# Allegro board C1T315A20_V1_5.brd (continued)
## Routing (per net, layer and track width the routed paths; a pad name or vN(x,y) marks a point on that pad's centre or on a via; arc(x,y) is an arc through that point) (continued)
TL_PA7_SWS: length 27.7
  TOP w0.2: U8.13 v1(30.27,47.78) ; R11.1 12.45,58.73 R36.1 v1(13.88,60.78)
  BOTTOM w0.2: v1(30.27,47.78) 26.59,47.78 13.88,60.5 v1(13.88,60.78)
TL_PB0: length 94.6
  TOP w0.2: 59.58,14.53 59.05,14.53 51.85,21.73 51.85,29.36 49.48,31.73 49.48,32.5 46.15,35.83 46.15,39.55 v1(46.58,39.98) ; v1(41.77,39.98) 34.01,39.98 31.23,42.77 31.23,44.67 30.62,45.27 U8.14 ; J3.3 J3.1
  BOTTOM w0.2: J3.3 70.65,53.3 67.55,56.41 59.24,56.41 58.49,57.16 54.66,57.16 49.05,51.55 49.05,42.45 v1(46.58,39.98) v1(41.77,39.98)
TL_PB1: length 60.3
  TOP w0.2: U8.15 30.98,45.41 31.58,44.81 31.58,42.91 33.98,40.5 v1(41.33,40.5) ; v1(46.15,40.5) 49.9,40.5 50.55,39.86 50.55,37.25 49.83,36.53 49.83,32.05 52.17,29.7 52.17,29.53 52.2,29.5 52.2,22.24 58.91,15.53 61.35,15.53 62.36,14.53 J6.33
  BOTTOM w0.2: v1(41.33,40.5) v1(46.15,40.5)
TL_PB2: length 52.5
  TOP w0.2: U8.16 31.33,45.56 31.92,44.96 31.92,43.05 33.98,41 v1(42.08,41) ; 59.58,17.07 57.87,17.07 52.55,22.38 52.55,29.82 50.17,32.19 50.17,36.35 50.9,37.08 50.9,40.05 49.95,41 v1(46.65,41)
  BOTTOM w0.2: v1(46.65,41) v1(42.08,41)
TL_PB3: length 58.4
  TOP w0.2: v1(46.15,41.5) 49.95,41.5 51.25,40.21 51.25,36.93 50.52,36.21 50.52,32.34 52.98,29.89 52.98,22.45 57.46,17.96 61.47,17.96 62.36,17.07 65.88,17.07 ; U8.17 31.67,45.7 32.27,45.1 32.27,43.2 33.97,41.5 v1(41.17,41.5)
  BOTTOM w0.2: v1(46.15,41.5) v1(41.17,41.5)
TL_PB4: length 49.2
  TOP w0.2: U8.18 32.02,45.85 32.62,45.25 32.62,43.34 33.97,42.01 v1(42.1,42.01) ; 59.58,19.61 58.83,19.61 53.33,25.11 53.33,30.03 50.88,32.48 50.88,36.06 51.6,36.79 51.6,40.38 49.98,42.01 v1(46.7,42.01)
  BOTTOM w0.2: v1(46.7,42.01) v1(42.1,42.01)
TL_PB5: length 55
  TOP w0.2: J6.29 65.33,19.61 63.69,21.24 58.09,21.24 53.73,25.61 53.73,30.24 51.23,32.74 51.23,35.92 51.95,36.64 51.95,40.56 49.88,42.63 v1(46.15,42.63) ; U8.19 32.38,45.99 32.98,45.4 32.98,43.49 34.11,42.35 41,42.35 v1(41.27,42.63)
  BOTTOM w0.2: v1(46.15,42.63) v1(41.27,42.63)
TL_PB6: length 47.2
  TOP w0.2: v1(46.75,43.13) 49.92,43.13 52.3,40.75 52.3,36.5 51.58,35.77 51.58,32.89 54.08,30.39 54.08,26.03 57.96,22.14 59.58,22.14 ; v1(42.05,43.13) 40.5,43.13 40.12,42.76 34.2,42.76 33.33,43.63 33.33,45.54 32.73,46.14 U8.20
  BOTTOM w0.2: v1(46.75,43.13) v1(42.05,43.13)
TL_PB7: length 53.2
  TOP w0.2: 65.88,22.14 65.21,22.14 64.31,23.05 57.55,23.05 54.48,26.12 54.48,30.48 51.92,33.03 51.92,35.63 52.65,36.35 52.65,40.91 49.78,43.78 v1(46.15,43.78) ; v1(41.65,43.78) 40.6,43.78 40.02,43.2 34.25,43.2 33.67,43.78 33.67,45.69 33.08,46.28 U8.21
  BOTTOM w0.2: v1(46.15,43.78) v1(41.65,43.78)
TL_PC0: length 35
  TOP w0.2: v1(53.12,34.55) 55.15,32.53 56.3,32.53 59.06,29.77 59.58,29.77 ; v1(39.23,43.74) 39.21,43.74 34.8,48.16 34.3,48.16
  BOTTOM w0.2: v1(53.12,34.55) 50.35,37.33 48.88,37.33 47.77,38.43 40.91,38.43 39.23,40.11 v1(39.23,43.74)
TL_PC1: length 34.5
  TOP w0.2: v1(39.83,44.24) 39.26,44.24 35,48.51 U8.25 ; v1(53.27,35.28) 55.65,32.91 58.33,32.91 58.92,32.3 59.58,32.3
  BOTTOM w0.2: v1(39.83,44.24) 39.8,44.21 39.8,43.91 39.8,43.91 39.8,43.5 39.8,43.5 39.8,40.03 41.05,38.78 47.92,38.78 49.02,37.68 50.88,37.68 v1(53.27,35.28)
TL_PC2: length 34.1
  TOP w0.2: v1(55.23,35.23) 58.01,35.23 58.39,34.84 59.58,34.84 ; v1(39.42,44.85) 39.35,44.85 39.35,44.83 39.17,44.83 35.15,48.85 U8.26
  BOTTOM w0.2: v1(55.23,35.23) 53.85,36.61 52.65,36.61 51.23,38.03 49.16,38.03 48.06,39.13 41.3,39.13 40.15,40.28 40.15,42.9 40.38,43.13 40.38,44.63 40.17,44.83 39.35,44.83 39.35,44.85 v1(39.42,44.85)
TL_PC3: length 33.4
  TOP w0.2: U8.27 35.29,49.2 39.14,45.35 v1(39.9,45.35) ; 59.58,37.39 59.17,36.98 v1(55.23,36.98)
  BOTTOM w0.2: v1(55.23,36.98) 52.81,36.98 51.42,38.38 49.31,38.38 48.21,39.48 41.5,39.48 40.5,40.48 40.5,42.76 40.77,43.03 40.77,44.76 40.17,45.35 v1(39.9,45.35)
TL_PC4_TDI: length 91.9
  TOP w0.2: v1(48.06,39.98) 47.35,39.27 v1(47.35,37.88) ; 59.58,42.47 59.4,42.28 v1(53.02,42.28) ; U8.32 35.81,50.95 36.71,50.05 39.23,50.05 43.08,46.2 43.08,39.86 40.75,37.53 40.75,37.31 v1(40.55,37.11) 39.82,36.38 18.48,36.38 18.12,36.73 16.9,36.73 v1(16.82,36.66)
  BOTTOM w0.2: v1(40.55,37.11) 40.84,37.41 46.88,37.41 v1(47.35,37.88) ; v1(53.02,42.28) 51.03,42.28 48.72,39.98 v1(48.06,39.98) ; v1(16.82,36.66) 16.82,43.73 8.3,52.26 8.3,53.21 7.5,54.01 5.63,54.01 J4.12
TL_PC5_TDO: length 89.6
  TOP w0.2: 40.62,36.33 40.62,36.25 40.55,36.25 40.33,36.03 18.33,36.03 18.13,36.23 v1(17.73,36.23) ; 40.62,36.33 40.62,36.41 41.1,36.88 41.1,37.39 43.42,39.71 43.42,46.35 39.37,50.41 36.85,50.41 35.95,51.3 U8.33 ; 40.62,36.33 v1(40.55,36.33) ; 59.58,39.92 58.15,39.92 57.1,38.88 v1(55.85,38.88) ; v1(49.67,39.98) 48.85,39.98 47.88,39 47.88,37.68 v1(47.4,37.2)
  BOTTOM w0.2: v1(17.73,36.23) 17.65,36.16 16.62,36.16 16.32,36.45 16.32,43.56 J4.11 ; v1(47.4,37.2) 47.25,37.05 41.2,37.05 40.55,36.41 v1(40.55,36.33) ; v1(49.67,39.98) 51.85,39.98 52.95,38.88 v1(55.85,38.88)
TL_PC6_TMS: length 113.8
  TOP w0.2: J6.11 65.31,42.47 61.62,38.78 57.73,38.78 57.2,38.25 v1(55.2,38.25) ; v1(46.65,36.55) 47.5,36.55 48.27,37.33 48.27,38.66 v1(49.08,39.45) ; 34.3,51.66 36.1,51.66 37,50.76 39.55,50.76 43.77,46.53 43.77,39.56 41.45,37.24 41.45,36.52 v1(41.31,36.37) 40.61,35.68 16.93,35.68 v1(16.75,35.5)
  BOTTOM w0.2: v1(49.08,39.45) 51.65,39.45 52.85,38.25 v1(55.2,38.25) ; v1(16.75,35.5) 15.97,36.28 15.97,43.41 7.83,51.55 4.16,51.55 3.33,52.38 3.33,55.87 4.01,56.55 5.07,56.55 5.63,57.11 5.63,61.87 J4.4 ; v1(41.31,36.37) 41.49,36.55 v1(46.65,36.55)
TL_PC7_TCK: length 112.7
  TOP w0.2: v1(41.31,35.67) 41.27,35.67 ; 41.27,35.67 41.27,35.7 41.38,35.7 41.85,36.18 41.85,37.14 44.12,39.42 44.12,46.67 39.7,51.1 37.15,51.1 36.24,52.01 U8.35 ; 41.27,35.67 40.94,35.33 18.02,35.33 v1(17.77,35.08) ; v1(47.05,36.05) 47.49,36.05 48.66,37.22 48.66,38.3 49.32,38.95 v1(49.7,38.95) ; v1(54.6,37.53) 57.17,37.53 57.95,38.3 63.7,38.3 65.32,39.92 J6.13
  BOTTOM w0.2: 4.49,60.48 1.72,57.72 1.72,52.93 3.45,51.2 7.69,51.2 15.62,43.27 15.62,35.92 16.54,35 17.7,35 v1(17.77,35.08) ; v1(41.31,35.67) 41.7,36.05 v1(47.05,36.05) ; v1(54.6,37.53) 52.83,37.53 51.4,38.95 v1(49.7,38.95)
TL_PD0_AMIC: length 72.8
  TOP w0.2: 59.58,6.9 59.58,9.45 59.11,9.45 58.12,10.43 58.12,11.91 45.27,24.76 45.27,55.51 42.5,58.28 37.28,58.28 36.99,58.57 36.98,58.57 36.25,59.3 33.11,59.3 30.62,56.82 U8.53
TL_PD1_MICBIAS: length 69
  TOP w0.2: 59.58,11.98 58.72,11.98 45.65,25.05 45.65,55.63 42.65,58.63 37.42,58.63 37.13,58.92 37.13,58.92 36.83,59.21 36.83,59.22 36.4,59.66 32.97,59.66 30.27,56.97 U8.54
TL_PD2_32K: length 16
  TOP w0.2: R34.2 39.33,62.01 C21.2 Y2.1 38.09,64.25 R1.1 37.42,63.8 35.66,62.04 35.66,61.22 34.45,60.01 32.82,60.01 29.92,57.11 U8.55
TL_PD2_NC_32K: length 48
  TOP w0.2: R34.1 41.15,62.01 46.73,56.43 46.73,47.25 49.85,44.13 49.92,44.13 53,41.05 53,36.21 52.27,35.48 52.27,33.18 54.98,30.48 54.98,26.12 56.41,24.69 59.58,24.69
TL_PD3_32K: length 18.5
  TOP w0.2: R35.2 39.62,64.24 Y2.2 ; Y2.2 38.4,65.52 C22.2 ; Y2.2 38.14,65.25 R1.2 36.62,64.45 36.62,63.53 35.31,62.22 35.31,61.37 34.3,60.35 32.67,60.35 29.58,57.26 U8.56
TL_PD3_NC_32K: length 45
  TOP w0.2: R35.1 47.08,56.58 47.08,47.4 49.99,44.48 50.07,44.48 53.35,41.2 53.35,36.06 52.62,35.34 52.62,33.32 55.33,30.62 55.33,30.32 58.42,27.23 59.58,27.23
TL_PD4: length 40.6
  TOP w0.2: v1(47.7,48.6) 47.7,49.2 50.45,51.95 56.37,51.95 59.58,55.16 ; v1(28.18,56.8) U8.60
  BOTTOM w0.2: v1(28.18,56.8) 27.7,56.8 C123.1 28.35,55.85 28.35,54.63 30.15,52.83 34.26,52.83 36.66,50.43 41.41,50.43 43.24,48.6 v1(47.7,48.6)
TL_PD5: length 37
  TOP w0.2: 59.58,50.09 50.08,50.09 48.35,48.35 v1(48.35,48.01) ; U8.61 v1(27.82,55.2)
  BOTTOM w0.2: 27.82,55.21 v1(27.82,55.2) 27.82,54.71 C124.1 27.83,54.6 29.95,52.48 34.11,52.48 36.51,50.08 41.27,50.08 43.34,48.01 v1(48.35,48.01)
TL_PD6: length 39.8
  TOP w0.2: v1(48.38,49.1) 50.77,51.51 57.9,51.51 59.02,52.62 59.58,52.62 ; v1(27.48,57.38) U8.62
  BOTTOM w0.2: v1(48.38,49.1) 43.25,49.1 41.58,50.78 36.8,50.78 34.4,53.18 30.3,53.18 28.7,54.77 28.7,56.81 C125.1 28.42,57.38 v1(27.48,57.38)
TL_PD7: length 38
  TOP w0.2: v1(47.7,47.48) 59.51,47.48 59.58,47.55 ; U8.63 v1(27.12,55.2)
  BOTTOM w0.2: v1(47.7,47.48) 43.38,47.48 41.12,49.73 36.37,49.73 33.97,52.13 28.1,52.13 27.32,52.91 27.32,54.16 C126.1 26.83,54.7 27.12,55 v1(27.12,55.2)
TL_PE0: length 26.6
  TOP w0.2: J7.2 4.26,47.66 5.88,49.28 12.36,49.28 18.23,55.16 25.2,55.16
TL_PE1: length 27.5
  TOP w0.2: J7.4 2.21,45.12 6.03,48.93 12.5,48.93 18.38,54.8 U8.68
TL_PE2: length 29.6
  TOP w0.2: U8.69 18.52,54.45 12.64,48.58 6.17,48.58 3.3,45.71 3.3,43.7 2.17,42.58 J7.6
TL_PE3: length 19.9
  TOP w0.2: U8.70 18.66,54.1 12.79,48.23 9.15,48.23 8.58,47.66 J7.1
TL_PE4: length 20.8
  TOP w0.2: J7.3 10.18,45.12 18.81,53.76 25.2,53.76
TL_PE5: length 22.7
  TOP w0.2: J7.5 9.85,42.58 12.2,44.93 12.2,46.62 18.98,53.41 U8.72
TL_PE6: length 24
  TOP w0.2: U8.73 19.13,53.05 12.55,46.48 12.55,44.66 10,42.1 10,41.53 8.51,40.04 J7.7
TL_PE7: length 26.1
  TOP w0.2: J7.9 8.47,37.5 9.43,38.45 9.43,40.46 10.35,41.39 10.35,41.96 12.9,44.51 12.9,46.33 19.27,52.7 U8.74
TL_PF0: length 34.8
  TOP w0.2: J7.8 2.19,40.04 5.63,36.6 9.28,36.6 9.85,37.17 9.85,39.45 10.95,40.55 10.95,42.03 13.25,44.34 13.25,46.19 19.42,52.35 U8.75
TL_PF1: length 33.9
  TOP w0.2: J7.10 2.23,37.5 3.48,36.25 9.42,36.25 10.2,37.03 10.2,39.31 11.3,40.41 11.3,41.89 13.6,44.19 13.6,46.04 19.57,52.01 U8.76
TL_PF2: length 33.7
  TOP w0.2: 25.2,51.66 19.71,51.66 13.95,45.9 13.95,44.05 11.65,41.75 11.65,40.27 10.55,39.16 10.55,36.88 9.55,35.88 3.15,35.88 2.23,34.96 1.67,34.96
TL_PF3: length 35.4
  TOP w0.2: 1.67,32.42 2.26,32.42 2.85,33 4.9,33 5.96,34.05 9.51,34.05 11.82,36.37 11.82,39.95 12,40.12 12,41.6 14.3,43.9 14.3,45.75 19.86,51.3 U8.78
TL_PF4: length 32
  TOP w0.2: 1.67,29.88 2.28,29.88 6.1,33.7 9.65,33.7 12.18,36.23 12.18,39.8 12.35,39.98 12.35,41.45 14.65,43.76 14.65,45.6 19.8,50.76 R44.1
TL_PF4_SDMP1: length 40.1
  TOP w0.2: TP6.1 41.9,19.33 L15.1 41.05,19.33 38.23,22.16 18.1,22.16 12.57,27.69 10.77,27.69 8.57,29.88 J7.15
TL_PF5: length 34
  TOP w0.2: 1.67,27.34 2.13,27.34 3.35,28.55 3.35,30.46 6.24,33.36 10.06,33.36 12.45,35.75 12.45,35.75 12.52,35.83 12.52,39.66 15.15,42.28 15.15,45.61 19.41,49.87 R45.1
TL_PF5_SDMN1: length 35.3
  TOP w0.2: TP7.1 38.2,19.31 L16.1 37.35,19.3 34.9,21.76 18,21.76 12.42,27.34 J7.17
TL_PF6: length 41.4
  TOP w0.2: 25.2,50.26 23.91,50.26 22.98,49.33 19.5,49.33 15.5,45.33 15.5,42.06 12.9,39.46 12.9,34.05 10.18,31.33 6.3,31.33 4.62,29.66 4.62,25.78 3.64,24.8 1.67,24.8
TL_PF7: length 42.3
  TOP w0.2: U8.82 24.05,49.91 23.13,48.98 19.65,48.98 15.85,45.18 15.85,41.88 13.3,39.33 13.3,33.96 10.22,30.88 6.53,30.88 4.97,29.33 4.97,25.56 1.67,22.26
TL_PG0_MOSI: length 13
  TOP w0.2: U2.5 25.5,37.59 24.15,38.93 24.15,43.08 24.8,43.73 26.51,43.73 28.18,45.4 U8.7
TL_PG1_MCLK: length 11.7
  TOP w0.2: 25.93,38.86 25.38,38.86 24.5,39.73 24.5,42.93 24.95,43.38 26.66,43.38 28.52,45.25 U8.8
TL_PG2_MSIO3: length 10.2
  TOP w0.2: U2.7 25.48,40.12 24.85,40.75 24.85,42.78 25.09,43.03 26.8,43.03 28.88,45.1 U8.9
TL_PG3_MSCN: length 47.2
  TOP w0.2: R3.2 21.27,43.63 ; 21.27,43.63 21.73,44.08 26.36,44.08 27.82,45.54 U8.6 ; 21.27,43.63 20.5,42.86 20.5,42.5 v1(20.52,42.48) 20.52,41.39 ; SW2.4 SW2.3 11.9,64.68 v1(11.9,63.73)
  BOTTOM w0.2: v1(11.9,63.73) 11.2,63.03 11.2,53.98 20.52,44.66 v1(20.52,42.48)
TL_PG4_MISO: length 13.6
  TOP w0.2: 20.52,40.12 20.05,40.12 19.43,40.75 19.43,42.28 21.57,44.43 26.22,44.43 27.48,45.69 U8.5
TL_PG5_MSIO2: length 14.8
  TOP w0.2: 20.52,38.86 19,40.38 19,42.35 21.43,44.78 26.07,44.78 27.12,45.83 U8.4
TL_RFVDD_0P94: length 68.7
  TOP w0.2: 26.23,56.85 26.23,56.83 26.43,56.63 U8.65
  TOP w0.3: 24.65,57.23 24.82,57.05 26.02,57.05 26.23,56.85
  TOP w0.5: 22.77,57.55 v1(22.13,57.55) ; 22.77,57.55 C9.1 ; 22.77,57.55 22.85,57.55 22.88,57.58 C8.1 D9.2 24.56,57.32 24.65,57.23
  POWER w0.5: v1(54.62,40.42) 54.51,40.3 52.91,40.3 52.52,39.92 52.52,39.81 46.29,33.58 25.23,33.58 v1(25.2,33.55) ; v1(22.13,57.55) 22.55,57.13 22.55,47.43 v1(22.05,46.93)
  BOTTOM w0.5: v1(25.2,33.55) 25.2,43.78 v1(22.05,46.93) ; 59.58,39.91 55.14,39.91 v1(54.62,40.42)
TL_VBAT: length 77.2
  TOP w0.2: U8.47 v1(32.73,55.2)
  POWER w0.5: v1(38.5,60.1) 39.73,61.33 43.45,61.33 46.52,58.26 54.58,58.26 57.02,55.8 v1(57.02,55.16) ; v1(54.15,39.38) 53.85,39.08 53.85,35.62 53.92,35.55 53.92,35.01 53.85,34.94 53.85,23.83 55.55,22.13 55.55,22.13 v1(55.55,22.13)
  BOTTOM w0.5: v1(54.15,39.38) 53.98,39.55 53.98,41.08 54.92,42.03 54.92,43.43 59.02,47.53 59.58,47.53 59.58,52.61 57.97,52.61 57.02,53.55 v1(57.02,55.16) ; v1(32.73,55.2) 33.02,55.51 D11.2 34.52,55.51 C17.1 35.58,56.55 35.58,58.58 37.1,60.1 v1(38.5,60.1) ; v1(55.55,22.13) 55.85,22.43 59.27,22.43 59.58,22.13 59.58,19.59
TL_VBUS: length 31.5
  TOP w0.2: U8.46 33.08,56.62 33.63,57.18
  TOP w0.35: 33.7,57.26 33.63,57.18
  TOP w0.5: v1(36.23,57.7) 35.77,57.26 33.7,57.26
  POWER w0.5: v1(40.08,60.66) 43,60.66 47.03,56.63 v1(55.05,56.63)
  BOTTOM w0.4: C20.1 40.08,59.85 v1(40.08,60.66) ; v1(36.23,57.7) D10.2
  BOTTOM w0.5: D10.2 C20.1 ; v1(55.05,56.63) 58.09,56.63 59.58,55.15
TL_VDD: length 34.2
  TOP w0.2: U8.66 26.07,56.27 25.88,56.47
  TOP w0.3: 24.43,56.58 25.77,56.58 25.88,56.47
  TOP w0.5: 24.43,56.58 C7.2 23.32,56.51 22.72,55.91 v1(20.73,55.91)
  POWER w0.5: v1(3.38,37.52) 5.78,39.91 5.78,42.41 19.27,55.91 v1(20.73,55.91)
  BOTTOM w0.5: v1(3.38,37.52) 1.67,37.52
TL_VDD0P94: length 44.4
  TOP w0.2: C30.1 37.52,53.76 34.3,53.76
  TOP w0.5: C30.1 v1(38.45,53.58)
  POWER w0.5: v1(38.45,53.58) 38.58,53.7 46.35,53.7 48.55,51.51 55.33,51.51 63.6,43.23 v1(63.6,39.91)
  BOTTOM w0.5: J9.18 J9.16 J9.14 63.64,39.91 63.64,39.91 v1(63.6,39.91)
TL_VDD3DCDC: length 47.3
  TOP w0.2: C32.1 39.8,51.8 37.44,51.8 36.53,52.7 U8.37
  TOP w0.3: C32.1 41,53.01 v1(42.6,53.01)
  POWER w0.5: v1(57.64,28.72) 55.88,30.48 55.88,37.73 56.5,38.36 56.5,43.8 54.17,46.13 46.48,46.13 42.6,50.01 v1(42.6,53.01)
  BOTTOM w0.5: v1(57.64,28.72) 59.15,27.21 59.58,27.21
TL_VDD_DMIC: length 94.5
  TOP w0.2: v1(42.42,24.28) 42.27,24.43 25.87,24.43 20.38,29.93 U6.6 ; U5.6 48.99,30.37 C41.1 48.1,30.86 v1(47.77,30.53)
  TOP w0.5: v1(23.35,32.55) 21,32.55 20.5,32.05 C42.1 20.48,31.94 20.48,30.55 U6.6 19.38,29.44 18.69,29.44 U6.2
  POWER w0.5: v1(58.09,33.89) 62.7,38.5 v1(62.7,42.95) ; v1(23.35,32.55) 24.27,31.63 51.23,31.63 v1(53.12,33.53)
  BOTTOM w0.2: v1(47.77,30.53) 47.77,29.66 42.42,24.3 v1(42.42,24.28)
  BOTTOM w0.5: v1(62.7,42.95) 64.73,44.99 J9.10 ; v1(53.12,33.53) 57.73,33.53 v1(58.09,33.89)
TL_VDD_F: length 38
  TOP w0.2: U8.43 35.48,54.8 35.65,54.98
  TOP w0.3: v1(43.95,55.16) 42.75,56.35 37.45,56.35 C24.1 36.48,55.8 35.65,54.98
  POWER w0.5: v1(64.4,43.41) 52.65,55.16 v1(43.95,55.16)
  BOTTOM w0.5: v1(64.4,43.41) 65.36,42.45 J9.12
TL_VDD_IR: length 26.1
  TOP w0.5: C36.2 52.77,61.2 v1(53.58,61.2) ; C36.2 R17.1 ; C36.2 51.23,60.26 R16.1 C37.2
  POWER w0.5: v1(53.58,61.2) 54.48,61.2 59.25,56.43 59.25,54.23 v1(63.45,50.03)
  BOTTOM w0.5: J9.8 65.42,47.53 63.45,49.51 v1(63.45,50.03)
TL_VDDCORE: length 44.9
  TOP w0.2: v1(38.4,47.6) 38.5,47.7 C29.1 38.55,48.18 37.41,48.18 35.33,50.26 34.3,50.26
  POWER w0.5: v1(38.4,47.6) 38.1,47.3 38.1,44.51 34.55,40.95 14.27,40.95 v1(13.5,41.73)
  BOTTOM w0.5: J8.2 8.92,47.67 13.5,43.1 v1(13.5,41.73)
TL_VDDDEC: length 54
  TOP w0.2: U8.31 35.5,50.6 36.48,49.63 37.02,49.63 C31.1
  TOP w0.5: v1(37.49,48.8) 37.27,49.02 C31.1
  POWER w0.5: v1(14.2,42.13) 14.65,41.68 34.13,41.68 37.38,44.93 37.38,48.69 v1(37.49,48.8)
  BOTTOM w0.5: J8.1 3.38,47.67 5.45,45.6 5.45,40.16 6.68,38.93 11.9,38.93 14.2,41.23 v1(14.2,42.13)
TL_VDDIO_AMS: length 66.9
  TOP w0.2: v1(31.92,56.81) 31.67,56.56 U8.50
  POWER w0.5: v1(31.92,56.81) 31.92,58.85 33.27,60.2 36.27,60.2 38.05,61.98 44.15,61.98 47.15,58.98 54.77,58.98 57.88,55.87 57.88,53.48 66.47,44.88 66.47,34.08 64.27,31.88 v1(62,31.88)
  BOTTOM w0.35: v1(31.92,56.81) 31.92,57.13 C14.1
  BOTTOM w0.5: 59.58,32.29 61.52,32.29 62,31.8 v1(62,31.88)
TL_VDDIO_PB: length 72.6
  TOP w0.2: C19.1 33.42,46.43 U8.22
  TOP w0.4: C19.1 v1(34.25,46.28)
  POWER w0.5: v1(4.7,8.61) 3.15,10.15 3.15,27.03 v1(3.47,27.36) 7.28,31.16 7.28,42.07 11.49,46.28 v1(34.25,46.28)
  BOTTOM w0.5: 7.97,7.04 7.29,7.04 5.72,8.61 v1(4.7,8.61) ; 1.67,27.36 v1(3.47,27.36)
TL_VDDIO_PC: length 72.9
  TOP w0.2: U8.23 34.58,47.8 34.77,47.6 34.77,46.08 C23.1
  TOP w0.4: C23.1 v1(35.25,46.28)
  POWER w0.5: 17.18,45.35 17.15,45.35 17.13,45.37 11.5,45.37 8.1,41.97 8.1,26.3 v1(4.08,22.28) ; 17.18,45.35 v1(17.18,45.63) ; 17.18,45.35 17.2,45.35 17.22,45.37 34.34,45.37 v1(35.25,46.28)
  BOTTOM w0.5: v1(4.08,22.28) 1.68,22.28 1.67,22.27 ; 7.03,57.94 7.03,57.45 17.18,47.3 v1(17.18,45.63)
TL_VDDIO_PD: length 89.3
  TOP w0.2: v1(29.2,55.2) 28.85,55.2 28.52,55.53 U8.59
  POWER w0.5: v1(3.8,17.2) 4.15,17.2 8.7,21.74 8.7,25.99 8.75,26.04 8.75,41.7 11.75,44.7 34.88,44.7 36.73,46.55 36.73,48.95 37.62,49.85 37.62,54.6 37.68,54.66 37.68,54.67 38.06,55.05 v1(42.65,55.05)
  BOTTOM w0.4: v1(29.2,55.2) 30,54.41 C10.2 30.15,54.16 30.65,53.66 34.52,53.66 36.7,55.83 41.88,55.83 v1(42.65,55.05)
  BOTTOM w0.5: v1(3.8,17.2) 1.67,17.2
TL_VDDIO_PEF: length 76.8
  TOP w0.2: v1(21.85,47.93) 21.52,48.26 C4.1 21.55,48.63 23.27,48.63 24.2,49.55 U8.83
  POWER w0.5: v1(21.85,47.93) 20.95,47.03 11.32,47.03 6.6,42.31 6.6,35.41 v1(3.67,32.48) ; v1(55.6,43.01) 55.6,43.3 53.42,45.48 42.67,45.48 v1(42.38,45.78)
  BOTTOM w0.5: v1(3.67,32.48) 3.63,32.44 1.67,32.44 ; v1(21.85,47.93) 22,47.93 22.98,46.95 41.2,46.95 v1(42.38,45.78) ; v1(55.6,43.01) 57.59,44.99 59.58,44.99
TL_VDDIO_USB: length 61
  TOP w0.2: U8.12 29.92,45.1 C12.1
  TOP w0.4: v1(30.73,42.38) 30.73,44.3 C12.1
  POWER w0.5: v1(30.73,42.38) 21.54,42.38 20.72,43.2 11.17,43.2 9.4,41.43 9.4,17.78 v1(3.88,12.25)
  BOTTOM w0.5: v1(3.88,12.25) 1.82,12.25 1.67,12.12
TL_VDDO1P8: length 43.9
  TOP w0.2: U8.28 35.54,49.55 38.29,46.8 C25.1
  TOP w0.5: C25.1 v1(39.02,46.3)
  POWER w0.5: v1(12.9,40.93) 13.38,40.93 14.01,40.3 34.82,40.3 38.77,44.26 38.77,46.05 v1(39.02,46.3)
  BOTTOM w0.5: J8.6 9.07,42.59 9.57,42.09 9.57,40.28 10.07,39.78 11.75,39.78 v1(12.9,40.93)
TL_VDDO3: length 154.1
  TOP w0.2: v1(32.61,56.81) 32.62,56.81 32.62,56.78 32.38,56.53 U8.48
  TOP w0.5: R7.2 59.17,59.35 55.54,55.72 v1(55.54,55.69)
  POWER w0.5: v1(33.66,57.91) 35.67,55.91 54.48,55.91 55.11,55.27 ; 55.11,55.27 57.88,52.5 57.88,52.48 65.8,44.55 65.8,34.38 v1(64,32.58) ; 55.11,55.27 v1(55.54,55.69) ; v1(41,22.33) 39.62,23.7 16.68,23.7 10.05,30.33 10.05,40.41 10.35,40.7 10.35,40.69 v1(10.36,40.69)
  BOTTOM w0.35: v1(33.66,57.91) 33.62,57.91 33.14,57.43 C18.1 33.12,57.32 v1(32.61,56.81)
  BOTTOM w0.5: 63.92,23.28 65.31,24.67 J9.26 J9.24 J9.22 J9.20 65.58,32.58 v1(64,32.58) ; 63.92,23.28 48.33,23.28 47.75,22.7 41.38,22.7 v1(41,22.33) ; 63.92,23.28 65.08,22.13 J9.28 ; v1(10.36,40.69) 10.35,40.69 10.35,42.76 J8.4
TL_VDDPST: length 43.1
  TOP w0.2: U8.36 36.39,52.35 37.29,51.45 C26.1
  TOP w0.3: C26.1 41.62,50.18 v1(43.4,50.18)
  POWER w0.5: v1(57.98,29.75) 56.67,31.05 56.67,37.18 57.23,37.73 57.23,44.1 54.5,46.83 46.75,46.83 v1(43.4,50.18)
  BOTTOM w0.5: v1(57.98,29.75) 59.58,29.75
TL_XC1: length 6.5
  TOP w0.2: U8.58 28.88,58.88 30.12,60.13 C5.2 30.73,60.87 Y1.3
TL_XC2: length 11
  TOP w0.2: U8.57 29.23,58.48 31.98,61.23 31.98,62.41 Y1.1 33.77,64.2 C6.2
USB_VBUS: length 10.6
  TOP w0.5: J2.B4A9 18.15,5.35 17.58,4.78 14.02,4.78 13.35,5.45 J2.A4B9 13.38,6.25 D12.2 C127.2 13.38,9.39 R9.2
VCOM: length 38
  TOP w0.5: R30.2 76.2,43.63 R31.1 76.17,43.51 76.11,43.51 74.75,42.15 v1(74.75,41.83)
  POWER w0.5: v1(61.25,17.05) 61.25,19.36 74.75,32.86 v1(74.75,41.83)
  BOTTOM w0.5: 59.58,14.51 59.58,17.05 v1(61.25,17.05)
VDW: length 38.3
  TOP w0.5: R31.2 76.25,41.63 R32.1 76.58,41.3 v1(76.92,41.3)
  POWER w0.5: v1(76.92,41.3) 76.58,41.3 76.2,40.93 76.2,27.43 v1(63.9,15.13)
  BOTTOM w0.5: J9.36 J9.34 64.52,14.51 v1(63.9,15.13)
VUP: length 37
  TOP w0.5: R29.2 76.17,45.55 R30.1 v1(76.82,45.58)
  POWER w0.5: v1(64.05,17.63) 64.05,21.24 75.4,32.59 75.4,33.05 75.45,33.11 75.45,44.28 76.75,45.58 v1(76.82,45.58)
  BOTTOM w0.5: J9.32 64.63,17.05 v1(64.05,17.63)
N20028206: length 3
  TOP w0.5: U7.1 74.2,44.48 74.22,44.51 R29.1 R33.1
N20230476: length 2.2
  TOP w0.2: Q1.1 33.8,26.96 33.8,26.95 R23.1 R19.2
N20230490: length 2.2
  TOP w0.2: Q2.1 38.86,26.88 R24.1 R20.2
N20230526: length 2.2
  TOP w0.2: Q3.1 34.26,30.81 R25.1 R21.2
N20230570: length 2.2
  TOP w0.2: Q4.1 38.86,30.63 R26.1 R22.2
N20230742: length 2
  TOP w0.2: R12.2 D1.A
N20230744: length 2.5
  TOP w0.2: D1.C 29.56,29.18 Q1.3
N20230746: length 2
  TOP w0.2: R13.2 D4.A
N20230748: length 10
  TOP w0.2: D4.C 30.49,25.8 35.55,25.8 36.66,26.91 Q2.3
N20230750: length 2
  TOP w0.2: R14.2 D2.A
N20230752: length 2.3
  TOP w0.2: D2.C 30.11,32.48 Q3.3
N20230754: length 2
  TOP w0.2: R15.2 D3.A
N20230756: length 9.2
  TOP w0.2: Q4.3 36.66,31.14 35.58,30.05 29.54,30.05 D3.C
N20248227: length 3.4
  TOP w0.2: C39.1 R18.2 48.74,17.68 49.42,17.68
N20254983: length 1.7
  TOP w0.2: 47.73,17.68 47.1,17.68 47.08,17.66 47.05,17.66 C38.1
N20255175: length 8.7
  TOP w0.2: J5.3 55.4,9.01 50.5,13.9 C40.1
N20271178: length 3.3
  TOP w0.5: R16.2 50.05,61.87 50.05,61.88 D5.A
N20271193: length 4.3
  TOP w0.5: D6.A 53.15,66.53 52.48,65.85 R17.2
N20286198: length 3.5
  TOP w0.2: R45.2 22.84,49.87 23.57,50.6 U8.80
N20286201: length 3.3
  TOP w0.2: U8.79 22.95,50.95 22.75,50.76 R44.2
N20286912: length 52.4
  TOP w0.2: v1(43.38,56.58) 42.02,57.93 37.13,57.93 36.84,58.22 36.84,58.22 36.1,58.95 33.26,58.95 30.98,56.67 U8.52 ; v1(58.77,60.6) 58.77,63.7 63.03,67.95 C11.1 65.97,67.95 SW1.1
  TOP w0.5: SW1.2 SW1.1
  BOTTOM w0.2: v1(58.77,60.6) 56.27,60.6 52.3,56.63 43.42,56.63 v1(43.38,56.58)
N20286959: length 3.2
  TOP w0.2: U8.51 v1(31.33,55.2)
  BOTTOM w0.3: v1(31.33,55.2) 29.75,56.78 C13.1
N20290975: length 9.2
  TOP w0.2: U8.38 36.68,53.05 37.41,52.33 37.58,52.33
  TOP w0.35: 39.26,52.33 37.58,52.33
  TOP w0.5: L2.2 41.75,54.03 41.27,53.55 40.48,53.55 39.26,52.33
N20290977: length 6.8
  TOP w0.2: U8.39 36.83,53.41 37.4,52.83 37.55,52.83
  TOP w0.35: 38.75,52.95 38.62,52.83 37.55,52.83
  TOP w0.5: 38.75,52.95 39.25,53.45 L2.1
N20305837: length 4
  TOP w0.2: R5.2 14.25,9.61 13.93,9.28 13.93,7.55 14.5,6.98 J2.A5
N20305839: length 1.6
  TOP w0.2: R10.2 J2.B5
N20310970: length 1.8
  TOP w0.5: L1.1 C2.1 C1.2
N20310976: length 1.6
  TOP w0.5: U1.4 C3.1 L1.2
N20348750: length 3.6
  BOTTOM w0.5: 2.51,55.66 2.51,56.89 3.55,57.94 4.49,57.94
N20353968: length 3.3
  TOP w0.2: R41.1 C73.1 C69.2 38.6,15.86 L16.2
N20353978: length 10.1
  TOP w0.2: R41.2 C75.2 39.5,9.91 39.5,9.9 35.58,5.98 35.58,4.58
N20354017: length 3.4
  TOP w0.2: L15.2 41.4,15.78 C115.1 C73.2 R40.1
N20354025: length 6
  TOP w0.2: J40.3 43.58,8.98 40.5,12.05 C76.1 R40.2
N20354127: length 3.4
  TOP w0.2: R43.1 C120.1 C117.2 26.15,15.96 L18.2
N20354137: length 9.9
  TOP w0.2: J41.2 23.45,7.63 27.05,11.23 C118.2 R43.2
N20354176: length 3.4
  TOP w0.2: R42.1 C120.2 C116.1 28.95,15.91 L17.2
N20354184: length 6.3
  TOP w0.2: J41.3 31.2,8.98 C119.1 R42.2
N20364573: length 4.6
  TOP w0.5: J1.1 D8.2 C45.1 U1.2
N20368232: length 1.3
  TOP w0.2: R36.2 U3.3
N20378065: length 4.8
  TOP w0.2: R47.2 21.24,47.43 22.7,47.43 24.48,49.2 U8.84
N20378070: length 5
  TOP w0.2: R46.2 21.23,46.43 22.26,46.43 24.68,48.85 U8.85
N202243015: length 1.4
  TOP w0.2: U3.4 13.88,54.51 R37.1
N202309440: length 2.9
  TOP w0.5: R8.1 75.5,59.38 75.49,59.37 J3.2
N202309690: length 3.1
  TOP w0.5: R7.1 69.52,59.35 69.53,59.37 J3.4

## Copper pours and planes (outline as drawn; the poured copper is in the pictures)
GND on TOP: 28.35,72.13 77.6,72.13 78.09,71.93 78.3,71.43 78.3,5.19 75.33,2.22 59.43,2.23 57.31,0.3 52.85,0.3 0,0.3 -0.49,0.51 -0.7,1 -0.7,71.43 -0.49,71.93 0,72.13 25.23,72.13 25.23,68.03 26.18,67.08 26.18,65.3 26.62,64.85 26.62,64.55 26.18,64.1 26.18,57.35 27.38,57.35 27.38,64.1 26.93,64.55 26.93,64.85 27.38,65.3 27.38,67.05 28.35,68.03 ; 36 cut-outs
GND on BOTTOM: 28.35,72.13 77.6,72.13 78.09,71.93 78.3,71.43 78.3,5.19 75.33,2.22 59.43,2.23 57.31,0.3 52.85,0.3 0,0.3 -0.49,0.51 -0.7,1 -0.7,71.43 -0.49,71.93 0,72.13 25.15,72.13 25.15,68 28.35,68 ; 17 cut-outs
GND on GND: -0.7,71.43 -0.49,71.93 0,72.13 77.6,72.13 78.09,71.93 78.3,71.43 78.3,5.19 75.33,2.22 59.43,2.23 57.31,0.3 52.85,0.3 0,0.3 -0.49,0.51 -0.7,1 ; 1 cut-out
GND on POWER: -0.7,71.43 -0.49,71.93 0,72.13 77.6,72.13 78.09,71.93 78.3,71.43 78.3,5.19 75.33,2.22 59.43,2.23 57.31,0.3 52.85,0.3 0,0.3 -0.49,0.51 -0.7,1 ; 5 cut-outs

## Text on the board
Ref Des/Silkscreen Bottom: NC | GND | VDD | DEC | VDDPD | VDDO3 | VDDPC | VDDPB | VDDUSB | VDDPEF | VDDO1P8 | LEVELSHIFT | CORE | TLVDDO3 | TLVDDO1P8 | TL7218X-EVK88D | 2025-05-23 | C1T315A20_V1.5 | VBAT | AVDD0P94 | VDDIOAMS | VDDPST | VDD3DCDC | AVDD3 | VCOM | TLVBUS | DVDD0P94 | RFVDD0P94 | FLASH | ADJ | VUP | 3V3 | VDW | VDDF | VBUS | VDDIR | VDD0P94 | VDDDMIC | LED_VBAT
User.Comments: #4 | #3 | #1 | #2 | TOP | #5
Ref Des/Silkscreen Top: SWS | TMS | TCK | TDI | VBUS | NC | 3V3 | TDO | VDDPC | GND | LINEIN | PA6 | PA5 | DM | DP | PF4 | PF5 | PF6 | PA3 | PA4 | PE0 | PE1 | PE2 | PF0 | PF1 | PF2 | PF3 | PF7 | PA0 | PA1 | PA2 | FLASH_RESET | SDMN1 | SDMP1 | PE3 | PE4 | PE5 | PE6 | PE7 | SDMP0 | SDMN0 | DMICDAT | DMICCK1 | DMICCK2 | IR_EX | PD4 | PD6 | PD5 | PD7 | PC4 | PC5 | PC3 | PC2 | PC1 | PC0 | PD3 | PD2 | PB6 | PB4 | PB2 | PB0 | PD1 | LEDG | PC6 | PC7 | LEDW | LEDR | LEDB | PB5 | PB3 | PB1 | KEY1 | KEY2 | KEY3 | KEY4 | PB7 | BIAS | IR | PD0 | MIC | CHIP_RESET
DISPLAY_TOP: FIGURE | FINISHED_SIZE | 0.2 | 0.3 | 0.5 | 0.7 | 0.9 | 1.0 | DRILL CHART: TOP to BOTTOM | ALL UNITS ARE IN MILLIMETERS | PLATED | NON-PLATED | QTY | 1 | 1355 | 2 | 4 | 12 | 6
